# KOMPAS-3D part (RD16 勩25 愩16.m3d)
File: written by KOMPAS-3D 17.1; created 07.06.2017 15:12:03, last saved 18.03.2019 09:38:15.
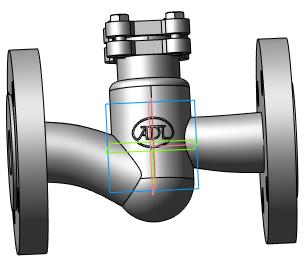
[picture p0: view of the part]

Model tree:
1. Операция без истории:2  (labels: Сталь 20  ГОСТ 1050-88)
